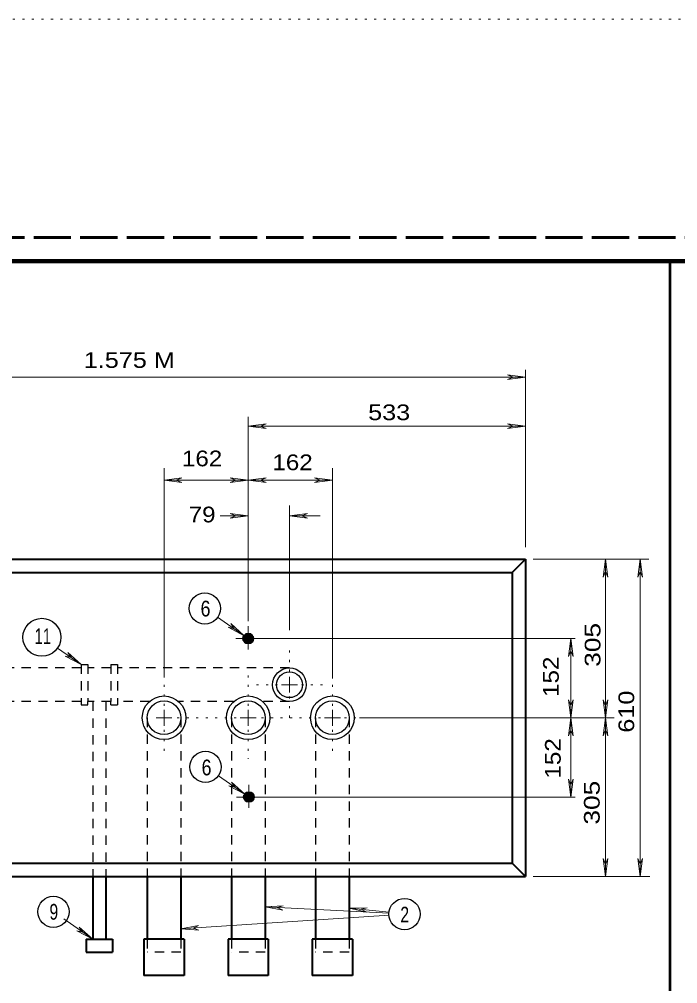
# Model space of a CAD drawing. Extents: x 312583 to 312854, y 144419 to 144597.
# Drawn here: x 312736.75 to 312768.6, y 144550.14 to 144596.78 of the extents above; entities that cross this region are included whole.
import ezdxf

# ---------------------------------------------------------------- set-up
doc = ezdxf.new("R2010")
doc.units = 0
doc.header["$LTSCALE"] = 0.3
for name, pattern in [('DOTTED', [1.5, 0.3, -1.2]), ('LONG_DASHED', [7.5, 6, -1.5]), ('SHORT_DASHED', [2.7, 1.5, -1.2])]:
    doc.linetypes.add(name, pattern=pattern)
for name, color, linetype, lineweight in [('1', 7, 'Continuous', 25), ('2', 7, 'Continuous', 13), ('63', 7, 'DOTTED', 13)]:
    doc.layers.add(name, color=color, linetype=linetype, lineweight=lineweight)

msp = doc.modelspace()

# ---------------------------------------------------------------- linework, layer by layer
at = {"layer": '1', "linetype": 'LONG_DASHED', "lineweight": 60}
msp.add_line((312851.75, 144586.2246), (312583.526, 144586.2246), dxfattribs=at)
at = {"layer": '1', "lineweight": 53}
msp.add_line((312768.237, 144506.4889), (312768.237, 144585.0846), dxfattribs=at)
at = {"layer": '1', "lineweight": 40}
for p, q in [((312721.6325, 144570.6666), (312761.2385, 144570.6666)), ((312760.6021, 144570.0303), (312761.2385, 144570.6666)), ((312761.2385, 144570.6666), (312761.2385, 144555.3333)), ((312722.2688, 144570.0303), (312760.6021, 144570.0303)), ((312760.6021, 144570.0303), (312760.6021, 144555.9773)), ((312722.2688, 144555.9773), (312760.6021, 144555.9773)), ((312760.6021, 144555.9773), (312761.2385, 144555.3333)), ((312721.6325, 144555.3333), (312761.2385, 144555.3333)), ((312740.3008, 144555.3333), (312740.3008, 144552.2973)), ((312740.9371, 144555.3333), (312740.9371, 144552.2973)), ((312742.9381, 144555.3333), (312742.9381, 144552.2973)), ((312744.5635, 144555.3333), (312744.5635, 144552.2973)), ((312747.0091, 144555.3333), (312747.0091, 144552.2973)), ((312748.6421, 144555.3333), (312748.6421, 144552.2973)), ((312751.0801, 144555.3333), (312751.0801, 144552.2973)), ((312752.7131, 144555.3333), (312752.7131, 144552.2973)), ((312739.9788, 144552.2973), (312741.2591, 144552.2973)), ((312739.9788, 144552.2973), (312739.9788, 144551.6609)), ((312741.2591, 144552.2973), (312741.2591, 144551.6609)), ((312742.7771, 144552.2973), (312742.7771, 144550.5416)), ((312744.7245, 144552.2973), (312742.7771, 144552.2973)), ((312744.7245, 144552.2973), (312744.7245, 144550.5416)), ((312746.8481, 144552.2973), (312746.8481, 144550.5416)), ((312748.7955, 144552.2973), (312746.8481, 144552.2973)), ((312748.7955, 144552.2973), (312748.7955, 144550.5416)), ((312750.9191, 144552.2973), (312750.9191, 144550.5416)), ((312752.8741, 144552.2973), (312750.9191, 144552.2973)), ((312752.8741, 144552.2973), (312752.8741, 144550.5416)), ((312739.9788, 144551.6609), (312741.2591, 144551.6609)), ((312744.7245, 144550.5416), (312742.7771, 144550.5416)), ((312748.7955, 144550.5416), (312746.8481, 144550.5416)), ((312752.8741, 144550.5416), (312750.9191, 144550.5416))]:
    msp.add_line(p, q, dxfattribs=at)
at = {"layer": '1', "linetype": 'SHORT_DASHED'}
for p, q in [((312739.7411, 144565.4149), (312730.2575, 144565.4149)), ((312739.7411, 144565.5759), (312739.7411, 144563.6286)), ((312739.7411, 144565.5759), (312740.0631, 144565.5759)), ((312740.0631, 144565.5759), (312740.0631, 144563.7819)), ((312741.1825, 144565.4149), (312740.0631, 144565.4149)), ((312741.1825, 144565.5759), (312741.1825, 144563.7819)), ((312741.1825, 144565.5759), (312741.4968, 144565.5759)), ((312741.4968, 144565.5759), (312741.4968, 144563.6286)), ((312749.8228, 144565.4149), (312741.4968, 144565.4149)), ((312739.7411, 144563.7819), (312730.2575, 144563.7819)), ((312739.7411, 144563.6286), (312740.0631, 144563.6286)), ((312740.0631, 144563.6286), (312740.0631, 144563.7819)), ((312741.1825, 144563.7819), (312740.0631, 144563.7819)), ((312740.3008, 144563.7819), (312740.3008, 144555.3333)), ((312740.9371, 144563.7819), (312740.9371, 144555.3333)), ((312741.1825, 144563.6286), (312741.1825, 144563.7819)), ((312741.1825, 144563.6286), (312741.4968, 144563.6286)), ((312743.0455, 144563.7819), (312741.4968, 144563.7819)), ((312747.1165, 144563.7819), (312744.4561, 144563.7819)), ((312749.8228, 144563.7819), (312748.5271, 144563.7819)), ((312742.9381, 144562.9999), (312742.9381, 144555.3333)), ((312744.5635, 144562.9999), (312744.5635, 144555.3333)), ((312747.0091, 144562.9999), (312747.0091, 144555.3333)), ((312748.6421, 144562.9999), (312748.6421, 144555.3333)), ((312751.0801, 144562.9999), (312751.0801, 144555.3333)), ((312752.7131, 144562.9999), (312752.7131, 144555.3333)), ((312742.9381, 144552.2973), (312742.9381, 144551.6609)), ((312744.5635, 144552.2973), (312744.5635, 144551.6609)), ((312747.0091, 144552.2973), (312747.0091, 144551.6609)), ((312748.6421, 144552.2973), (312748.6421, 144551.6609)), ((312751.0801, 144552.2973), (312751.0801, 144551.6609)), ((312752.7131, 144552.2973), (312752.7131, 144551.6609)), ((312744.5635, 144551.6609), (312742.9381, 144551.6609)), ((312748.6421, 144551.6609), (312747.0091, 144551.6609)), ((312752.7131, 144551.6609), (312751.0801, 144551.6609))]:
    msp.add_line(p, q, dxfattribs=at)
at = {"layer": '1', "lineweight": 158}
msp.add_lwpolyline([(312616.5, 144423.1446), (312616.5, 144585.0846), (312849, 144585.0846)], dxfattribs=at)
at = {"layer": '1', "lineweight": 40}
for centre, radius in [((312747.8237, 144566.8352), 0.2396), ((312747.8237, 144566.8352), 0.2156), ((312747.8237, 144566.8352), 0.1941), ((312747.8237, 144566.8352), 0.1747), ((312747.8237, 144566.8352), 0.1572), ((312747.8237, 144566.8352), 0.1415), ((312747.8237, 144566.8352), 0.1273), ((312747.8237, 144566.8352), 0.1146), ((312747.8237, 144566.8352), 0.1031), ((312747.8237, 144566.8352), 0.0928), ((312747.8237, 144566.8352), 0.0835), ((312747.8237, 144566.8352), 0.0752), ((312747.8237, 144566.8352), 0.0677), ((312747.8237, 144566.8352), 0.0609), ((312747.8237, 144566.8352), 0.0548), ((312747.8557, 144559.1685), 0.2396), ((312747.8557, 144559.1685), 0.2156), ((312747.8557, 144559.1685), 0.1941), ((312747.8557, 144559.1685), 0.1747), ((312747.8557, 144559.1685), 0.1572), ((312747.8557, 144559.1685), 0.1415), ((312747.8557, 144559.1685), 0.1273), ((312747.8557, 144559.1685), 0.1146), ((312747.8557, 144559.1685), 0.1031), ((312747.8557, 144559.1685), 0.0928), ((312747.8557, 144559.1685), 0.0835), ((312747.8557, 144559.1685), 0.0752), ((312747.8557, 144559.1685), 0.0677), ((312747.8557, 144559.1685), 0.0609), ((312747.8557, 144559.1685), 0.0548)]:
    msp.add_circle(centre, radius, dxfattribs=at)
at = {"layer": '1'}
for centre, radius in [((312749.8202, 144564.5991), 0.8146), ((312749.8202, 144564.5991), 0.6232), ((312743.7508, 144563.0019), 1.0542), ((312743.7508, 144563.0019), 0.8146), ((312747.8237, 144563.0019), 1.0542), ((312747.8237, 144563.0019), 0.8146), ((312751.8966, 144563.0019), 1.0542), ((312751.8966, 144563.0019), 0.8146)]:
    msp.add_circle(centre, radius, dxfattribs=at)
at = {"layer": '2'}
for p, q in [((312761.2385, 144571.2569), (312761.2385, 144579.8359)), ((312721.6325, 144579.4756), (312761.2385, 144579.4756)), ((312760.3721, 144579.5829), (312760.6481, 144579.4756)), ((312761.2385, 144579.4756), (312760.3721, 144579.5829)), ((312760.3721, 144579.3683), (312760.6481, 144579.4756)), ((312761.2385, 144579.4756), (312760.3721, 144579.3683)), ((312747.8218, 144567.6766), (312747.8218, 144577.5589)), ((312747.8218, 144577.1066), (312748.6881, 144577.2139)), ((312747.8218, 144577.1066), (312761.2385, 144577.1066)), ((312747.8218, 144577.1066), (312748.6881, 144576.9993)), ((312748.6881, 144577.2139), (312748.4121, 144577.1066)), ((312748.6881, 144576.9993), (312748.4121, 144577.1066)), ((312760.3721, 144577.2139), (312760.6481, 144577.1066)), ((312761.2385, 144577.1066), (312760.3721, 144577.2139)), ((312760.3721, 144576.9993), (312760.6481, 144577.1066)), ((312761.2385, 144577.1066), (312760.3721, 144576.9993)), ((312743.7508, 144564.9933), (312743.7508, 144575.0749)), ((312751.9005, 144564.9013), (312751.9005, 144575.0749)), ((312743.7508, 144574.4923), (312744.6171, 144574.5996)), ((312744.6171, 144574.5996), (312744.3411, 144574.4923)), ((312746.9555, 144574.5996), (312747.2315, 144574.4923)), ((312747.8218, 144574.4923), (312746.9555, 144574.5996)), ((312747.8218, 144574.4923), (312748.6881, 144574.5996)), ((312748.6881, 144574.5996), (312748.4121, 144574.4923)), ((312751.0341, 144574.5996), (312751.3101, 144574.4923)), ((312751.9005, 144574.4923), (312751.0341, 144574.5996)), ((312743.7508, 144574.4923), (312744.6171, 144574.3849)), ((312743.7508, 144574.4923), (312747.8218, 144574.4923)), ((312744.6171, 144574.3849), (312744.3411, 144574.4923)), ((312746.9555, 144574.3849), (312747.2315, 144574.4923)), ((312747.8218, 144574.4923), (312746.9555, 144574.3849)), ((312747.8218, 144574.4923), (312751.9005, 144574.4923)), ((312747.8218, 144574.4923), (312748.6881, 144574.3849)), ((312748.6881, 144574.3849), (312748.4121, 144574.4923)), ((312751.0341, 144574.3849), (312751.3101, 144574.4923)), ((312751.9005, 144574.4923), (312751.0341, 144574.3849)), ((312749.8228, 144567.2319), (312749.8228, 144573.2733)), ((312746.4725, 144572.7673), (312747.8218, 144572.7673)), ((312746.9555, 144572.8746), (312747.2315, 144572.7673)), ((312747.8218, 144572.7673), (312746.9555, 144572.8746)), ((312746.9555, 144572.6599), (312747.2315, 144572.7673)), ((312747.8218, 144572.7673), (312746.9555, 144572.6599)), ((312749.8228, 144572.7673), (312750.6891, 144572.8746)), ((312749.8228, 144572.7673), (312751.3025, 144572.7673)), ((312749.8228, 144572.7673), (312750.6891, 144572.6599)), ((312750.6891, 144572.8746), (312750.4131, 144572.7673)), ((312750.6891, 144572.6599), (312750.4131, 144572.7673)), ((312761.6141, 144570.6666), (312767.2103, 144570.6666)), ((312765.1114, 144570.6666), (312765.004, 144569.8003)), ((312765.1114, 144570.6666), (312765.2187, 144569.8003)), ((312766.7849, 144570.6666), (312766.6775, 144569.8003)), ((312766.7849, 144570.6666), (312766.8922, 144569.8003)), ((312766.7849, 144555.3333), (312766.7849, 144570.6666)), ((312765.004, 144569.8003), (312765.1114, 144570.0763)), ((312765.2187, 144569.8003), (312765.1114, 144570.0763)), ((312766.6775, 144569.8003), (312766.7849, 144570.0763)), ((312766.8922, 144569.8003), (312766.7849, 144570.0763)), ((312746.3421, 144567.8606), (312747.6301, 144566.9713)), ((312746.9785, 144567.5539), (312747.1395, 144567.3086)), ((312747.6301, 144566.9713), (312746.9785, 144567.5539)), ((312746.8558, 144567.3776), (312747.1395, 144567.3086)), ((312747.6301, 144566.9713), (312746.8558, 144567.3776)), ((312747.8218, 144566.3119), (312747.8218, 144567.4313)), ((312748.3508, 144566.8333), (312747.2238, 144566.8333)), ((312747.9445, 144566.8333), (312763.6458, 144566.8333)), ((312763.4311, 144566.8333), (312763.3238, 144565.9669)), ((312763.4311, 144566.8333), (312763.5385, 144565.9669)), ((312738.5911, 144566.3733), (312739.7411, 144565.5759)), ((312739.0895, 144566.1586), (312739.2581, 144565.9133)), ((312739.7411, 144565.5759), (312739.0895, 144566.1586)), ((312763.3238, 144565.9669), (312763.4311, 144566.2429)), ((312763.5385, 144565.9669), (312763.4311, 144566.2429)), ((312738.9668, 144565.9823), (312739.2581, 144565.9133)), ((312739.7411, 144565.5759), (312738.9668, 144565.9823)), ((312749.8228, 144564.6023), (312749.8228, 144564.9856)), ((312749.8228, 144564.6023), (312749.4395, 144564.6023)), ((312749.8228, 144564.6023), (312750.2061, 144564.6023)), ((312749.8228, 144564.6023), (312749.8228, 144564.2189)), ((312763.3238, 144563.8663), (312763.4311, 144563.5903)), ((312763.4311, 144562.9999), (312763.3238, 144563.8663)), ((312763.5385, 144563.8663), (312763.4311, 144563.5903)), ((312763.4311, 144562.9999), (312763.5385, 144563.8663)), ((312765.004, 144563.8663), (312765.1114, 144563.5903)), ((312765.1114, 144562.9999), (312765.004, 144563.8663)), ((312765.2187, 144563.8663), (312765.1114, 144563.5903)), ((312765.1114, 144562.9999), (312765.2187, 144563.8663)), ((312743.7508, 144562.9999), (312743.7508, 144563.3833)), ((312747.8218, 144562.9999), (312747.8218, 144563.3833)), ((312751.9005, 144562.9999), (312751.9005, 144563.3833)), ((312743.7508, 144562.9999), (312743.3675, 144562.9999)), ((312743.7508, 144562.9999), (312744.1341, 144562.9999)), ((312743.7508, 144562.9999), (312743.7508, 144562.6166)), ((312747.8218, 144562.9999), (312747.4385, 144562.9999)), ((312747.8218, 144562.9999), (312748.2051, 144562.9999)), ((312747.8218, 144562.9999), (312747.8218, 144562.6166)), ((312751.9005, 144562.9999), (312751.5171, 144562.9999)), ((312751.9005, 144562.9999), (312752.2838, 144562.9999)), ((312751.9005, 144562.9999), (312751.9005, 144562.6166)), ((312753.2038, 144562.9999), (312765.5291, 144562.9999)), ((312763.4311, 144562.9999), (312763.3238, 144562.1336)), ((312763.4311, 144562.9999), (312763.5385, 144562.1336)), ((312765.1114, 144562.9999), (312765.004, 144562.1336)), ((312765.1114, 144562.9999), (312765.2187, 144562.1336)), ((312763.3238, 144562.1336), (312763.4311, 144562.4096)), ((312763.5385, 144562.1336), (312763.4311, 144562.4096)), ((312765.004, 144562.1336), (312765.1114, 144562.4096)), ((312765.2187, 144562.1336), (312765.1114, 144562.4096)), ((312746.3805, 144560.1939), (312747.6608, 144559.3046)), ((312746.8865, 144559.7109), (312747.1778, 144559.6419)), ((312747.6608, 144559.3046), (312746.8865, 144559.7109)), ((312747.0091, 144559.8873), (312747.1778, 144559.6419)), ((312747.6608, 144559.3046), (312747.0091, 144559.8873)), ((312747.8525, 144558.6453), (312747.8525, 144559.7646)), ((312763.3238, 144560.0329), (312763.4311, 144559.7569)), ((312763.4311, 144559.1666), (312763.3238, 144560.0329)), ((312763.5385, 144560.0329), (312763.4311, 144559.7569)), ((312763.4311, 144559.1666), (312763.5385, 144560.0329)), ((312748.3815, 144559.1666), (312747.2621, 144559.1666)), ((312747.9445, 144559.1666), (312763.6458, 144559.1666)), ((312765.004, 144556.1996), (312765.1114, 144555.9236)), ((312765.1114, 144555.3333), (312765.004, 144556.1996)), ((312765.2187, 144556.1996), (312765.1114, 144555.9236)), ((312765.1114, 144555.3333), (312765.2187, 144556.1996)), ((312766.6775, 144556.1996), (312766.7849, 144555.9236)), ((312766.7849, 144555.3333), (312766.6775, 144556.1996)), ((312766.6775, 144556.1996), (312766.7849, 144555.9236)), ((312766.7849, 144555.3333), (312766.6775, 144556.1996)), ((312766.8922, 144556.1996), (312766.7849, 144555.9236)), ((312766.7849, 144555.3333), (312766.8922, 144556.1996)), ((312766.8922, 144556.1996), (312766.7849, 144555.9236)), ((312766.7849, 144555.3333), (312766.8922, 144556.1996)), ((312761.6141, 144555.3333), (312767.2477, 144555.3333)), ((312748.6421, 144553.8536), (312749.5085, 144553.9149)), ((312748.6421, 144553.8536), (312754.6375, 144553.5469)), ((312748.6421, 144553.8536), (312749.5008, 144553.7003)), ((312749.5085, 144553.9149), (312749.2248, 144553.8229)), ((312749.5008, 144553.7003), (312749.2248, 144553.8229)), ((312752.7131, 144553.7999), (312753.5871, 144553.8153)), ((312754.6375, 144553.5929), (312752.7131, 144553.7999)), ((312752.7131, 144553.7999), (312753.5641, 144553.6006)), ((312753.5871, 144553.8153), (312753.2958, 144553.7386)), ((312753.5641, 144553.6006), (312753.2958, 144553.7386)), ((312738.8978, 144553.2786), (312740.3008, 144552.2973)), ((312754.6375, 144553.4626), (312744.5635, 144552.7879)), ((312739.5265, 144552.7036), (312739.8178, 144552.6346)), ((312740.3008, 144552.2973), (312739.5265, 144552.7036)), ((312739.6491, 144552.8799), (312739.8178, 144552.6346)), ((312740.3008, 144552.2973), (312739.6491, 144552.8799)), ((312744.5635, 144552.7879), (312745.4221, 144552.9489)), ((312744.5635, 144552.7879), (312745.4375, 144552.7343)), ((312745.4221, 144552.9489), (312745.1538, 144552.8263)), ((312745.4375, 144552.7343), (312745.1538, 144552.8263))]:
    msp.add_line(p, q, dxfattribs=at)
at = {"layer": '2', "linetype": 'DOTTED'}
for p, q in [((312749.8228, 144565.2386), (312749.8228, 144566.4346)), ((312743.7508, 144563.5749), (312743.7508, 144564.9933)), ((312747.8218, 144563.5749), (312747.8218, 144565.0469)), ((312751.9005, 144563.5749), (312751.9005, 144564.9013)), ((312749.2478, 144564.6023), (312748.0441, 144564.6023)), ((312750.3978, 144564.6023), (312751.5708, 144564.6023)), ((312749.8228, 144564.0273), (312749.8228, 144562.9386)), ((312747.2468, 144562.9999), (312744.3795, 144562.9999)), ((312751.3255, 144562.9999), (312748.4428, 144562.9999)), ((312752.4755, 144562.9999), (312753.8401, 144562.9999)), ((312743.7508, 144562.4249), (312743.7508, 144561.1369)), ((312747.8218, 144562.4249), (312747.8218, 144561.0143)), ((312751.9005, 144562.4249), (312751.9005, 144561.1063))]:
    msp.add_line(p, q, dxfattribs=at)
at = {"layer": '2'}
for points in [[(312765.1114, 144555.3333), (312765.1114, 144562.9999), (312765.1114, 144570.6666)], [(312763.4311, 144559.1666), (312763.4311, 144562.9999), (312763.4311, 144566.8333)]]:
    msp.add_lwpolyline(points, dxfattribs=at)
at = {"layer": '2', "lineweight": 25}
for centre, radius in [((312745.725, 144568.2919), 0.7557), ((312737.8398, 144566.8933), 0.9185), ((312745.7569, 144560.6252), 0.7557), ((312738.3988, 144553.6204), 0.7557), ((312755.3894, 144553.5092), 0.7557)]:
    msp.add_circle(centre, radius, dxfattribs=at)
at = {"layer": '63'}
msp.add_line((312601.2, 144596.7846), (312853.5, 144596.7846), dxfattribs=at)

# ---------------------------------------------------------------- texts
at = {"layer": '2'}
for s, width, p in [('1.575 M', 1.2, (312739.8673, 144579.9233)), ('533 ', 1.2, (312753.6261, 144577.3962)), ('162 ', 1.15, (312744.6184, 144575.1644)), ('162 ', 1.15, (312748.9944, 144574.9775)), ('79 ', 1.15, (312744.9435, 144572.453)), ('6', 0.85, (312745.5181, 144567.9038)), ('11', 0.7, (312737.4916, 144566.5645)), ('6', 0.85, (312745.5674, 144560.2185)), ('9', 0.75, (312738.2087, 144553.2375)), ('2', 0.75, (312755.1835, 144553.1038))]:
    msp.add_text(s, height=0.76, dxfattribs=dict(at, width=width)).set_placement(p)
for s, width, p in [('305 ', 1.25, (312764.8653, 144565.469)), ('152 ', 1.15, (312762.8488, 144564.0104)), ('610 ', 1.2, (312766.4967, 144562.2812)), ('152 ', 1.15, (312762.9422, 144560.0617)), ('305 ', 1.25, (312764.8281, 144557.8369))]:
    msp.add_text(s, height=0.76, rotation=90, dxfattribs=dict(at, width=width)).set_placement(p)

doc.saveas('drawing.dxf')
